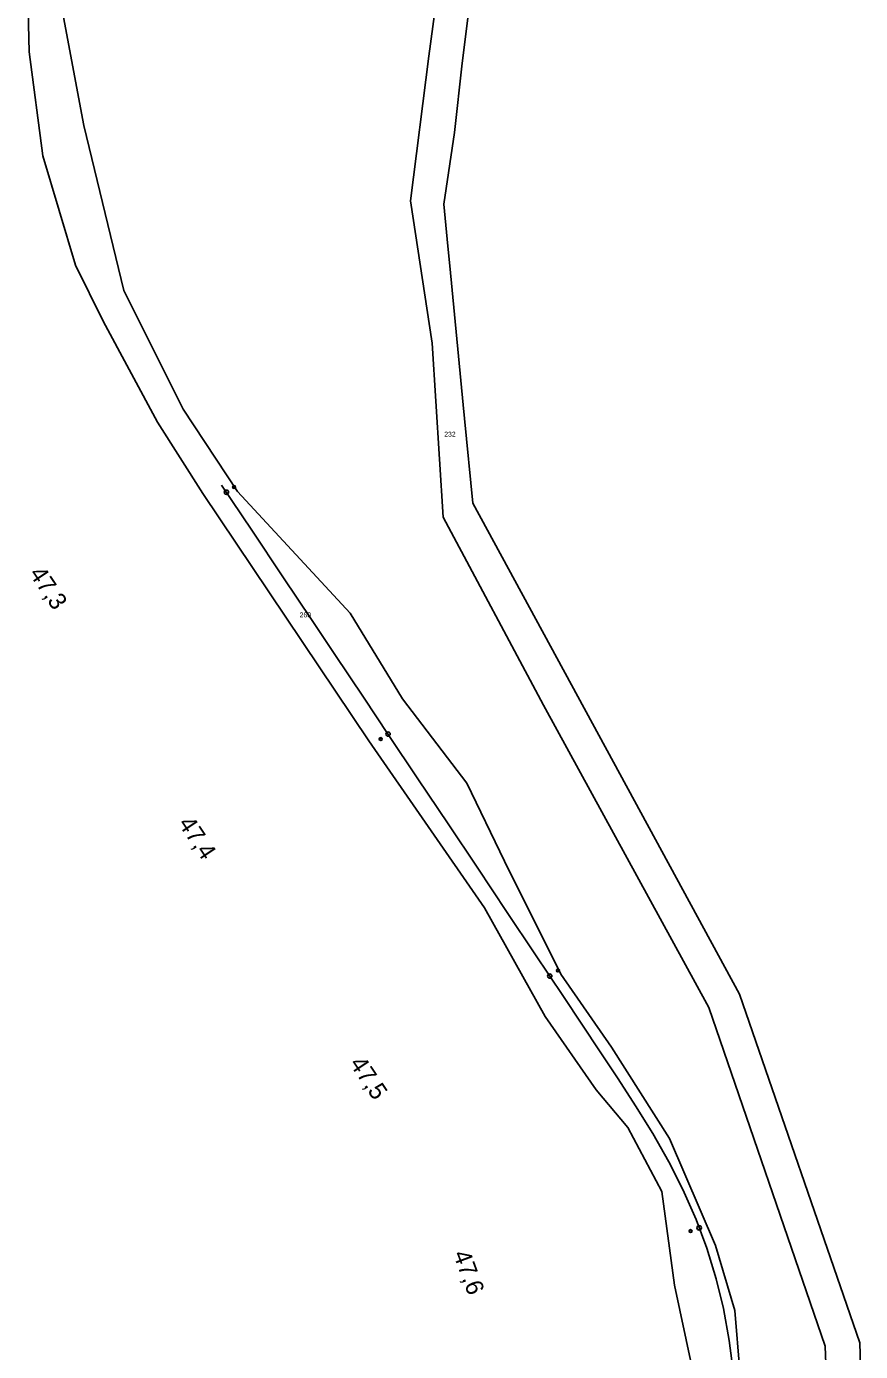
# Model space of a CAD drawing. Extents: x -811039 to -805820, y -1161436 to -1155864.
# Drawn here: x -806883.1 to -806596.4, y -1157247.5 to -1156792.1 of the extents above; entities that cross this region are included whole.
import ezdxf

# ---------------------------------------------------------------- set-up
doc = ezdxf.new("R2010")
doc.units = 0
for name, color, linetype in [('KN_HRANICE', 7, 'Continuous'), ('KN_PARCELY', 7, 'Continuous'), ('kú', 7, 'Continuous'), ('Vrstva 1', 7, 'Continuous'), ('Vrstva 7', 7, 'Continuous')]:
    doc.layers.add(name, color=color, linetype=linetype)

msp = doc.modelspace()

# ---------------------------------------------------------------- linework, layer by layer
at = {"layer": 'KN_HRANICE'}
for p, q in [((-806744.78, -1156802.3), (-806730.44, -1156693.59)), ((-806882.16, -1156800.83), (-806883.1, -1156763.58)), ((-806728.01, -1156761.63), (-806733.33, -1156804.71)), ((-806863.43, -1156826.1), (-806871.36, -1156783.41)), ((-806877.47, -1156836.54), (-806882.16, -1156800.83)), ((-806751.07, -1156852.07), (-806744.78, -1156802.3)), ((-806733.33, -1156804.71), (-806735.92, -1156828.57)), ((-806849.6, -1156882.81), (-806863.43, -1156826.1)), ((-806735.92, -1156828.57), (-806739.62, -1156853.19)), ((-806866.24, -1156874.09), (-806877.47, -1156836.54)), ((-806743.7, -1156900.98), (-806751.07, -1156852.07)), ((-806739.62, -1156853.19), (-806738.21, -1156867.58)), ((-806738.21, -1156867.58), (-806737.53, -1156874.37)), ((-806856.73, -1156893.43), (-806866.24, -1156874.09)), ((-806737.53, -1156874.37), (-806732.94, -1156922.16)), ((-806849.6, -1156882.81), (-806829.26, -1156923.63)), ((-806838.09, -1156928.07), (-806856.73, -1156893.43)), ((-806739.84, -1156960.75), (-806743.7, -1156900.98)), ((-806829.26, -1156923.63), (-806810.62, -1156951.87)), ((-806732.94, -1156922.16), (-806732.49, -1156926.83)), ((-806822.44, -1156952.58), (-806838.09, -1156928.07)), ((-806732.49, -1156926.83), (-806729.7, -1156955.88)), ((-806765.4, -1157037.63), (-806822.44, -1156952.58)), ((-806729.7, -1156955.88), (-806637.99, -1157124.69)), ((-806705.39, -1157025.32), (-806739.84, -1156960.75)), ((-806753.81, -1157023.16), (-806731.72, -1157052.21)), ((-806648.5, -1157129.28), (-806705.39, -1157025.32)), ((-806725.65, -1157094.98), (-806765.4, -1157037.63)), ((-806731.72, -1157052.21), (-806718.79, -1157078.98)), ((-806718.79, -1157078.98), (-806699.45, -1157117.78)), ((-806704.84, -1157132.38), (-806725.65, -1157094.98)), ((-806699.45, -1157117.78), (-806682.02, -1157142.9)), ((-806637.99, -1157124.69), (-806596.67, -1157244.46)), ((-806687.24, -1157157.56), (-806704.84, -1157132.38)), ((-806608.57, -1157245.67), (-806648.5, -1157129.28)), ((-806682.02, -1157142.9), (-806662.11, -1157174.22)), ((-806676.4, -1157170.49), (-806687.24, -1157157.56)), ((-806664.75, -1157192.47), (-806676.4, -1157170.49)), ((-806662.11, -1157174.22), (-806646.28, -1157211.08)), ((-806660.37, -1157224.72), (-806664.75, -1157192.47)), ((-806646.28, -1157211.08), (-806639.66, -1157233.41)), ((-806654.56, -1157252.05), (-806660.37, -1157224.72)), ((-806639.66, -1157233.41), (-806637.89, -1157254.23)), ((-806606.13, -1157309.82), (-806608.57, -1157245.67))]:
    msp.add_line(p, q, dxfattribs=at)
msp.add_lwpolyline([(-806810.62, -1156951.87), (-806771.81, -1156993.75), (-806753.81, -1157023.16)], dxfattribs=at)
at = {"layer": 'kú'}
msp.add_line((-806596.67, -1157244.46), (-806596.41, -1157252.34), dxfattribs=at)
at = {"layer": 'Vrstva 1'}
for points in [[(-806816.03, -1156949.73), (-806805.68, -1156965.18), (-806794.97, -1156981.2), (-806784.89, -1156996.28), (-806777.34, -1157007.57), (-806767.08, -1157022.89), (-806758.72, -1157035.42), (-806748.56, -1157050.61), (-806738.16, -1157066.15), (-806728.17, -1157081.08), (-806717.82, -1157096.57), (-806708.31, -1157110.84), (-806698.55, -1157125.51), (-806685.91, -1157144.43), (-806679.67, -1157153.8)], [(-806679.67, -1157153.8), (-806673.71, -1157163), (-806667.83, -1157172.53), (-806662.29, -1157182.29), (-806657.45, -1157191.8), (-806652.95, -1157202.08), (-806649.28, -1157211.94), (-806646.03, -1157222.51), (-806643.53, -1157232.65), (-806641.51, -1157243.64), (-806640.1, -1157255.04), (-806639.38, -1157266.73), (-806639.26, -1157278.63), (-806639.53, -1157289.83), (-806640.09, -1157301.8), (-806640.67, -1157311.27)]]:
    msp.add_lwpolyline(points, dxfattribs=at)
at = {"layer": 'Vrstva 7'}
for p, q in [((-806811.77, -1156950.34), (-806811.72, -1156950.42)), ((-806761.38, -1157036.96), (-806761.33, -1157037.04)), ((-806700.42, -1157116.5), (-806700.37, -1157116.59)), ((-806654.85, -1157206.02), (-806654.81, -1157206.12))]:
    msp.add_line(p, q, dxfattribs=at)
for centre, radius in [((-806811.74, -1156950.38), 0.5), ((-806814.4, -1156952.16), 0.75), ((-806761.35, -1157037), 0.5), ((-806758.81, -1157035.29), 0.75), ((-806703.25, -1157118.44), 0.75), ((-806700.4, -1157116.55), 0.5), ((-806654.83, -1157206.07), 0.5), ((-806651.87, -1157204.97), 0.75)]:
    msp.add_circle(centre, radius, dxfattribs=at)

# ---------------------------------------------------------------- texts
at = {"layer": 'KN_PARCELY'}
for s, p in [('232', (-806739.5, -1156933.08)), ('260', (-806789.2, -1156995.17))]:
    msp.add_text(s, height=1.7, dxfattribs=at).set_placement(p)
at = {"layer": 'Vrstva 7'}
for s, rotation, p in [('47,3', 303.8207, (-806882.37, -1156980.15)), ('47,4', 303.7312, (-806831.15, -1157066.04)), ('47,5', 303.6405, (-806772.24, -1157148.52)), ('47,6', 290.4196, (-806736.54, -1157213.93))]:
    msp.add_text(s, height=6, rotation=rotation, dxfattribs=at).set_placement(p)

doc.saveas('drawing.dxf')
